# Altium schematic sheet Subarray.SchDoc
size 431 x 279 mm; SheetNumber: 2; SheetTotal: 4; PageSetup: Record=PageOptions¦CenterHorizontal=True¦CenterVertical=True¦PrintScale=1.01¦XCorrection=1.00¦YCorrection=1.00¦PrintKind=1¦BorderSize=5000000¦LeftOffset=0¦BottomOffset=0¦Orientation=2¦PaperLength=1000¦PaperWidth=1000¦Scale=100¦PaperSource=7¦PrintQuality=600¦MediaType=1¦DitherType=10¦PaperKind=A3¦PrintScaleMode=1; ENG_APP_DATE: --/--/--; DSN_APP_DATE: --/--/--; CHK_APP_DATE: --/--/--
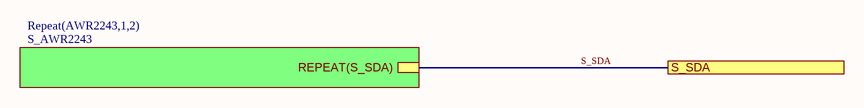
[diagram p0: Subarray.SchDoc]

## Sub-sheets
Repeat(AWR2243,1,2) = S_AWR2243: REPEAT(S_SDA)

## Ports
S_SDA

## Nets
S_SDA: port S_SDA, sheet Repeat(AWR2243,1,2)/REPEAT(S_SDA)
